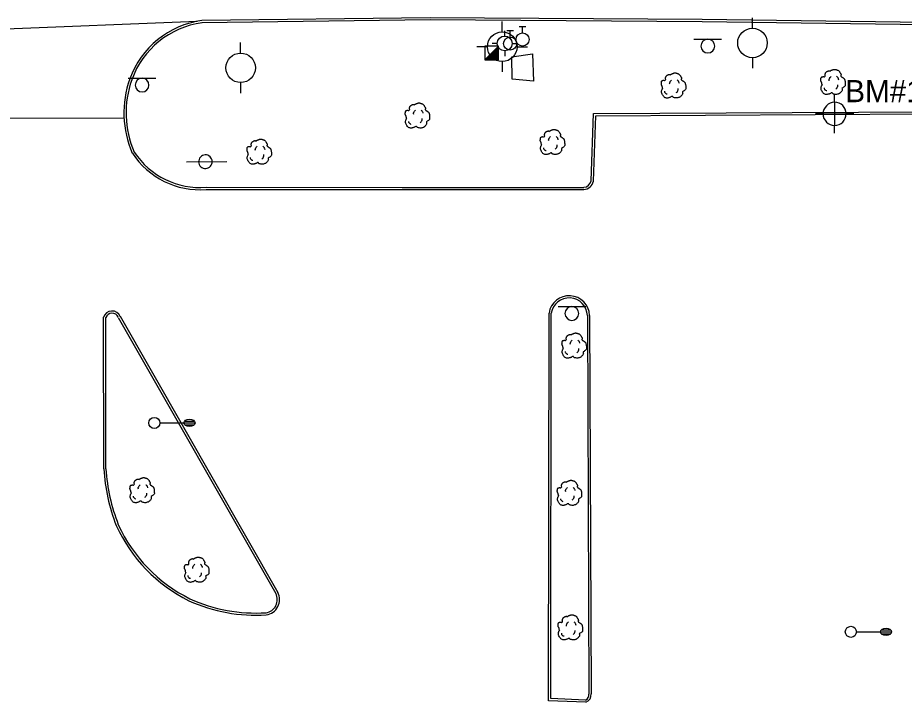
# Model space of a CAD drawing. Extents: x 2145380 to 2157287, y 139568 to 149130.
# Drawn here: x 2146114.3 to 2146354, y 142742.8 to 142927.9 of the extents above; entities that cross this region are included whole.
import ezdxf

# ---------------------------------------------------------------- set-up
doc = ezdxf.new("R2010")
doc.units = 0
for name, color, linetype in [('Default', 7, 'Continuous'), ('SURV_Benchmark', 7, 'Continuous'), ('TOPO_Asphalt', 7, 'Continuous'), ('TOPO_Concrete', 7, 'Continuous'), ('TOPO_Curb Back', 7, 'Continuous'), ('TOPO_Light Pole', 7, 'Continuous'), ('TOPO_Misc', 7, 'Continuous'), ('TOPO_Power Pole', 7, 'Continuous'), ('TOPO_Sign', 7, 'Continuous'), ('TOPO_Tree', 7, 'Continuous'), ('TOPO_Water Fire Hydrant', 7, 'Continuous'), ('TOPO_Water Valve', 7, 'Continuous')]:
    doc.layers.add(name, color=color, linetype=linetype)

# ---------------------------------------------------------------- blocks, each defined once
blk = doc.blocks.new('FIRHYD')
at = {"layer": 'TOPO_Water Fire Hydrant'}
for p, q in [((-0.02, 10.16), (-0.03, 17.34)), ((10.16, 0.02), (17.34, 0.03)), ((-10.16, -0.02), (-17.34, -0.03)), ((0.02, -10.16), (0.03, -17.34))]:
    blk.add_line(p, q, dxfattribs=at)
blk.add_circle((0, 0), 10.16, dxfattribs=at)
blk = doc.blocks.new('LP')
at = {"layer": 'TOPO_Light Pole'}
blk.add_line((3.81, 0), (20.32, 0), dxfattribs=at)
for points in [[(20.32, 0), (27.94, 0)], [(20.32, 0), (23.5, 0)], [(20.83, 1.27), (27.43, 1.27)], [(20.83, 1.27), (23.5, 1.27)], [(23.71, 1.27), (27.43, 1.27)], [(23.71, 0), (27.94, 0)], [(20.83, -1.27), (27.43, -1.27)], [(20.83, -1.27), (23.5, -1.27)], [(23.71, -1.27), (27.43, -1.27)]]:
    blk.add_lwpolyline(points, dxfattribs=at)
blk.add_circle((0, 0), 3.81, dxfattribs=at)
blk.add_ellipse((24.13, 0), major_axis=(3.81, 0), ratio=0.666667, dxfattribs=at)
blk = doc.blocks.new('TREE')
at = {"layer": 'TOPO_Tree'}
for points in [[(-14.1, -0.4), (-14.2, 0.5), (-14.4, 1.4), (-14.6, 2.3), (-14.8, 3.2), (-15.5, 4), (-15.7, 4.9), (-15.8, 5.6), (-15.7, 6.3), (-15.7, 7), (-15.6, 7.9), (-15.7, 8.8), (-15.1, 9.7), (-14.6, 10.4), (-13.8, 10.5), (-13, 10.7), (-12.2, 11), (-11.1, 10), (-10.4, 10.7), (-9.4, 11.7), (-10.3, 13.3), (-9.8, 14.4), (-9.6, 15.1), (-9.3, 15.9), (-8.8, 16.5), (-8.2, 17.3), (-7.5, 17.7), (-6.7, 18.1), (-6.1, 18.4), (-5.6, 18.6), (-5.1, 18.7), (-4.5, 18.7), (-4, 18.5), (-3.5, 18.1)], [(-3.5, 17.6), (-3.1, 18.3), (-2.6, 18.8), (-1.9, 19.2), (-1, 19.7), (-0.2, 20), (0.7, 20.2), (1.6, 20.5), (2.5, 20.8), (3.4, 20.8), (4.1, 20.7), (4.8, 20.5), (5.5, 20.2), (6.4, 19.9), (7.3, 19.7), (8.2, 19.2), (9.4, 18.4), (10, 17.2), (10.8, 16), (11.2, 15.3), (11.6, 14.6), (11.9, 13.9), (12.2, 13.1), (11.4, 12), (11.9, 11.2), (12, 11), (12.2, 10.9), (12.4, 10.7), (12.9, 10.4), (13.5, 10), (14, 9.7), (14.7, 9.2), (15.4, 8.7), (16.1, 8.1), (16.7, 7.5), (16.9, 6.7), (17.1, 6), (17.6, 4.4), (17.7, 2.8), (17.7, 1.2), (17.7, -0.2), (17.8, -2.2), (16.6, -3), (15.5, -3.8), (14.3, -4.6), (13.2, -5.3)], [(13.2, -5.3), (13.3, -5.8), (13.4, -6.3), (13.4, -6.7), (13.8, -8.5), (12.2, -10), (10.8, -11.5), (10, -12.3), (9.1, -12.8), (8.2, -13.1), (6, -13.8), (3.3, -13.6), (1.3, -13.1), (0.5, -12.9), (-0.1, -11.4), (-0.8, -11.5), (-2, -11.6), (-3.3, -12.8), (-4.5, -13.1), (-6.1, -13.5), (-7.8, -14), (-9.3, -13.6), (-11.4, -13.1), (-12.8, -11.4), (-14.1, -9.4), (-15.3, -7.3), (-15.6, -5.1), (-15.1, -3), (-14.9, -1.9), (-13.9, -0.8), (-13.5, 0.1)], [(-4.2, 5.1), (-4.5, 6.1), (-4.3, 7.2), (-3.8, 8.2), (-3.3, 9.3), (-2.7, 10.3), (-1.6, 11)], [(5.9, 11.2), (6.5, 10.7), (7, 10.2), (7.4, 9.5), (7.9, 8.6), (8.3, 7.6), (8.5, 6.6)], [(-11.4, -4.5), (-11.5, -5.4), (-11, -6.3), (-10.1, -7.2), (-9.3, -8), (-8.5, -8.3), (-7.7, -8.1)], [(4.8, -6.3), (5.7, -5.7), (6.3, -4.9), (6.8, -3.9), (7.4, -2.8), (7.6, -1.7), (7.5, -0.6)]]:
    blk.add_open_spline(points, degree=3, dxfattribs=at)
blk = doc.blocks.new('POWPOL')
at = {"layer": 'TOPO_Power Pole'}
for p, q in [((0, 10.16), (0, 17.34)), ((0, -10.16), (0, -17.34))]:
    blk.add_line(p, q, dxfattribs=at)
blk.add_circle((0, 0), 10.16, dxfattribs=at)
blk = doc.blocks.new('WATVAL')
at = {"layer": 'Default'}
for p, q in [((-2.25, 9), (2.25, 9)), ((0, 4.5), (0, 9))]:
    blk.add_line(p, q, dxfattribs=at)
blk.add_circle((0, 0), 4.5, dxfattribs=at)
blk = doc.blocks.new('BM')
at = {"layer": 'SURV_Benchmark'}
for p, q in [((0, 2.49), (0, 4.15)), ((-2.49, 0), (-4.16, 0)), ((4.16, 0), (2.49, 0)), ((0, -4.16), (0, -2.49))]:
    blk.add_line(p, q, dxfattribs=at)
for points in [[(0, 2.49), (0, 2.49), (0, 0), (2.49, 0), (2.49, 0), (2.49, 0)], [(0, 2.49), (0, 2.49), (0, 0), (2.49, 0), (2.49, 0), (2.49, 0), (2.49, 0)], [(-2.5, 0), (-2.49, 0), (0, 0), (0, -2.49), (0, -2.49)], [(-2.5, 0), (-2.49, 0), (0, 0), (0, -2.49), (0, -2.49)]]:
    blk.add_lwpolyline(points, dxfattribs=at)
for start, end in [(90.0638, 180.0068), (0.0638, 90.0068), (0.0638, 90.0068), (180.0638, 270.0068), (180.0638, 270.0068), (269.9472, 359.9927)]:
    blk.add_arc((0, 0), 2.5, start, end, dxfattribs=at)

msp = doc.modelspace()

# ---------------------------------------------------------------- linework, layer by layer
at = {"layer": 'TOPO_Asphalt'}
msp.add_line((2146162.81, 142926.9), (2146088.05, 142923.82), dxfattribs=at)
msp.add_lwpolyline([(2146143.08, 142900.75), (2146109.53, 142900.6), (2146108.01, 142840.92)], dxfattribs=at)
at = {"layer": 'TOPO_Concrete'}
msp.add_lwpolyline([(2146247.93, 142917.29), (2146253.44, 142918.08), (2146253.72, 142910.71), (2146248, 142911.27), (2146247.93, 142917.29)], dxfattribs=at)
at = {"layer": 'TOPO_Curb Back'}
for p, q in [((2146225.83, 142927.89), (2146164.1, 142927.11)), ((2146225.83, 142927.29), (2146164.14, 142926.51)), ((2146299.3, 142927.39), (2146225.83, 142927.89)), ((2146299.3, 142926.79), (2146225.83, 142927.29)), ((2146367.28, 142926.46), (2146299.3, 142927.39)), ((2146367.27, 142925.86), (2146299.3, 142926.79)), ((2146269.99, 142901.99), (2146399.83, 142902.69)), ((2146269.36, 142883.77), (2146269.99, 142901.99)), ((2146269.96, 142883.7), (2146270.57, 142901.4)), ((2146270.57, 142901.4), (2146399.24, 142902.08)), ((2146165.27, 142882.03), (2146218.21, 142882.02)), ((2146165.29, 142881.43), (2146218.21, 142881.42)), ((2146218.21, 142882.02), (2146267.35, 142882.02)), ((2146218.21, 142881.42), (2146267.37, 142881.42)), ((2146257.79, 142743.2), (2146257.95, 142848.04)), ((2146258.39, 142743.78), (2146258.55, 142847.99)), ((2146268.31, 142847.39), (2146268.71, 142745.03)), ((2146268.91, 142847.41), (2146269.31, 142745.08)), ((2146267.92, 142742.79), (2146257.79, 142743.2)), ((2146267.82, 142743.4), (2146258.39, 142743.78))]:
    msp.add_line(p, q, dxfattribs=at)
for points in [[(2146142.03, 142847.16), (2146184.63, 142772.5)], [(2146137.59, 142805.89), (2146137.52, 142846.93)], [(2146138.19, 142805.91), (2146138.12, 142846.82)], [(2146141.51, 142846.87), (2146184.11, 142772.21)]]:
    msp.add_lwpolyline(points, dxfattribs=at)
for centre, radius, start, end in [((2146167.36, 142903.14), 24.19, 97.7413, 160.1992), ((2146167.36, 142903.14), 23.59, 97.8302, 160.1944), ((2146170.47, 142902.21), 27.44, 160.5719, 203.4978), ((2146170.47, 142902.21), 26.84, 160.576, 203.3896), ((2146163.6, 142903.21), 21.84, 213.1349, 274.4329), ((2146163.6, 142903.21), 21.24, 213.2712, 274.4953), ((2146267.16, 142884.27), 2.25, 274.7408, 347.3117), ((2146267.16, 142884.27), 2.85, 274.2133, 348.5068), ((2146263.4, 142847.2), 5.52, 2.1523, 171.1976), ((2146263.4, 142847.2), 4.92, 2.2667, 170.68), ((2146139.83, 142846.16), 2.43, 23.7339, 161.5912), ((2146139.83, 142846.16), 1.83, 23.7339, 158.7359), ((2146188.23, 142809.04), 50.74, 183.5572, 201.3357), ((2146188.23, 142809.04), 50.14, 183.5778, 201.3163), ((2146179.58, 142808.23), 42.46, 204.5635, 243.453), ((2146179.58, 142808.23), 41.86, 204.5867, 243.4387), ((2146178.68, 142809.79), 42.87, 245.4541, 273.6945), ((2146180.89, 142770.57), 3.61, 278.8125, 26.9815), ((2146180.89, 142770.57), 4.21, 278.435, 27.1831), ((2146178.68, 142809.79), 43.47, 245.4402, 273.7286), ((2146267.27, 142744.75), 1.46, 292.2463, 10.8513), ((2146267.27, 142744.75), 2.06, 288.3246, 9.1709)]:
    msp.add_arc(centre, radius, start, end, dxfattribs=at)
at = {"layer": 'TOPO_Misc'}
for p, q in [((2146240.56, 142916.46), (2146244.3, 142920.21)), ((2146243.15, 142919.06), (2146244.3, 142919.06)), ((2146243.33, 142919.24), (2146244.3, 142919.24)), ((2146243.52, 142919.43), (2146244.3, 142919.43)), ((2146243.71, 142919.62), (2146244.3, 142919.62)), ((2146243.89, 142919.81), (2146244.3, 142919.81)), ((2146244.09, 142920), (2146244.3, 142920)), ((2146244.27, 142920.18), (2146244.3, 142920.18)), ((2146240.72, 142916.63), (2146244.3, 142916.63)), ((2146240.91, 142916.82), (2146244.3, 142916.82)), ((2146241.09, 142917), (2146244.3, 142917)), ((2146241.28, 142917.19), (2146244.3, 142917.19)), ((2146241.46, 142917.37), (2146244.3, 142917.37)), ((2146241.65, 142917.56), (2146244.3, 142917.56)), ((2146241.84, 142917.76), (2146244.3, 142917.76)), ((2146242.03, 142917.94), (2146244.3, 142917.94)), ((2146242.22, 142918.13), (2146244.3, 142918.13)), ((2146242.4, 142918.31), (2146244.3, 142918.31)), ((2146242.58, 142918.49), (2146244.3, 142918.49)), ((2146242.77, 142918.68), (2146244.3, 142918.68)), ((2146242.96, 142918.87), (2146244.3, 142918.87))]:
    msp.add_line(p, q, dxfattribs=at)
msp.add_lwpolyline([(2146244.3, 142916.47), (2146244.3, 142920.21), (2146240.55, 142920.21), (2146240.56, 142916.46), (2146244.3, 142916.47)], dxfattribs=at)
at = {"layer": 'TOPO_Sign'}
for points in [[(2146297.11, 142922.09), (2146304.61, 142922.1)], [(2146300.86, 142922.09), (2146300.86, 142922.09)], [(2146298.99, 142920.23), (2146298.99, 142920.23)], [(2146302.73, 142920.23), (2146302.73, 142920.23)], [(2146300.86, 142918.36), (2146300.86, 142918.36)], [(2146144.19, 142911.56), (2146151.68, 142911.56)], [(2146146.07, 142909.69), (2146146.07, 142909.69)], [(2146147.94, 142911.55), (2146147.94, 142911.55)], [(2146149.81, 142909.69), (2146149.81, 142909.69)], [(2146147.94, 142907.82), (2146147.94, 142907.82)], [(2146159.93, 142888.94), (2146170.81, 142889)], [(2146260.38, 142849.8), (2146267.87, 142849.8)], [(2146264.13, 142849.8), (2146264.13, 142849.8)], [(2146262.26, 142847.93), (2146262.26, 142847.93)], [(2146266, 142847.93), (2146266, 142847.93)], [(2146264.13, 142846.06), (2146264.13, 142846.06)]]:
    msp.add_lwpolyline(points, dxfattribs=at)
for centre, radius, start, end in [((2146300.86, 142920.23), 1.87, 90, 180), ((2146300.86, 142920.23), 1.87, 360, 90), ((2146300.86, 142920.23), 1.87, 180, 270), ((2146300.86, 142920.23), 1.87, 270, 0), ((2146147.94, 142909.69), 1.87, 90, 180), ((2146147.94, 142909.69), 1.87, 180, 270), ((2146147.94, 142909.69), 1.87, 360, 90), ((2146147.94, 142909.69), 1.87, 270, 0), ((2146165.07, 142888.96), 1.84, 47.4196, 227.4196), ((2146165.07, 142888.96), 1.84, 227.4196, 47.4196), ((2146264.13, 142847.93), 1.87, 90, 180), ((2146264.13, 142847.93), 1.87, 360, 90), ((2146264.13, 142847.93), 1.87, 180, 270), ((2146264.13, 142847.93), 1.87, 270, 0)]:
    msp.add_arc(centre, radius, start, end, dxfattribs=at)

# ---------------------------------------------------------------- block references
at = {"layer": 'SURV_Benchmark', "xscale": 1.25, "yscale": 1.25}
msp.add_blockref('BM', (2146335.15, 142901.9), dxfattribs=at)
at = {"layer": 'TOPO_Light Pole', "xscale": 0.39370000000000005, "yscale": 0.3937000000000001}
for p in [(2146151.26, 142818.33), (2146339.54, 142761.84)]:
    msp.add_blockref('LP', p, dxfattribs=at)
at = {"layer": 'TOPO_Power Pole', "xscale": 0.39370000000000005, "yscale": 0.3937000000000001}
for p in [(2146312.94, 142921.06), (2146174.59, 142914.34)]:
    msp.add_blockref('POWPOL', p, dxfattribs=at)
at = {"layer": 'TOPO_Tree', "xscale": 0.19685000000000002, "yscale": 0.19685000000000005}
for p in [(2146291.41, 142908.88), (2146334.53, 142909.84), (2146222.19, 142900.75), (2146258.69, 142893.6), (2146179.41, 142890.98), (2146264.55, 142838.55), (2146147.77, 142799.45), (2146263.28, 142798.73), (2146162.53, 142777.95), (2146263.52, 142762.36)]:
    msp.add_blockref('TREE', p, dxfattribs=at)
at = {"layer": 'TOPO_Water Fire Hydrant'}
for p, xscale, yscale in [((2146245.3, 142920.05), 0.39370000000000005, 0.3937000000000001), ((2146245.97, 142920.93), 0.19685000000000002, 0.19685000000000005)]:
    msp.add_blockref('FIRHYD', p, dxfattribs=dict(at, xscale=xscale, yscale=yscale))
at = {"layer": 'TOPO_Water Valve', "xscale": 0.39370000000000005, "yscale": 0.3937000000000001}
for p in [(2146247.45, 142920.89), (2146250.8, 142922)]:
    msp.add_blockref('WATVAL', p, dxfattribs=at)

# ---------------------------------------------------------------- texts
at = {"layer": 'SURV_Benchmark'}
msp.add_text('BM#16', height=6, dxfattribs=at).set_placement((2146338.02, 142905.05))

doc.saveas('drawing.dxf')
